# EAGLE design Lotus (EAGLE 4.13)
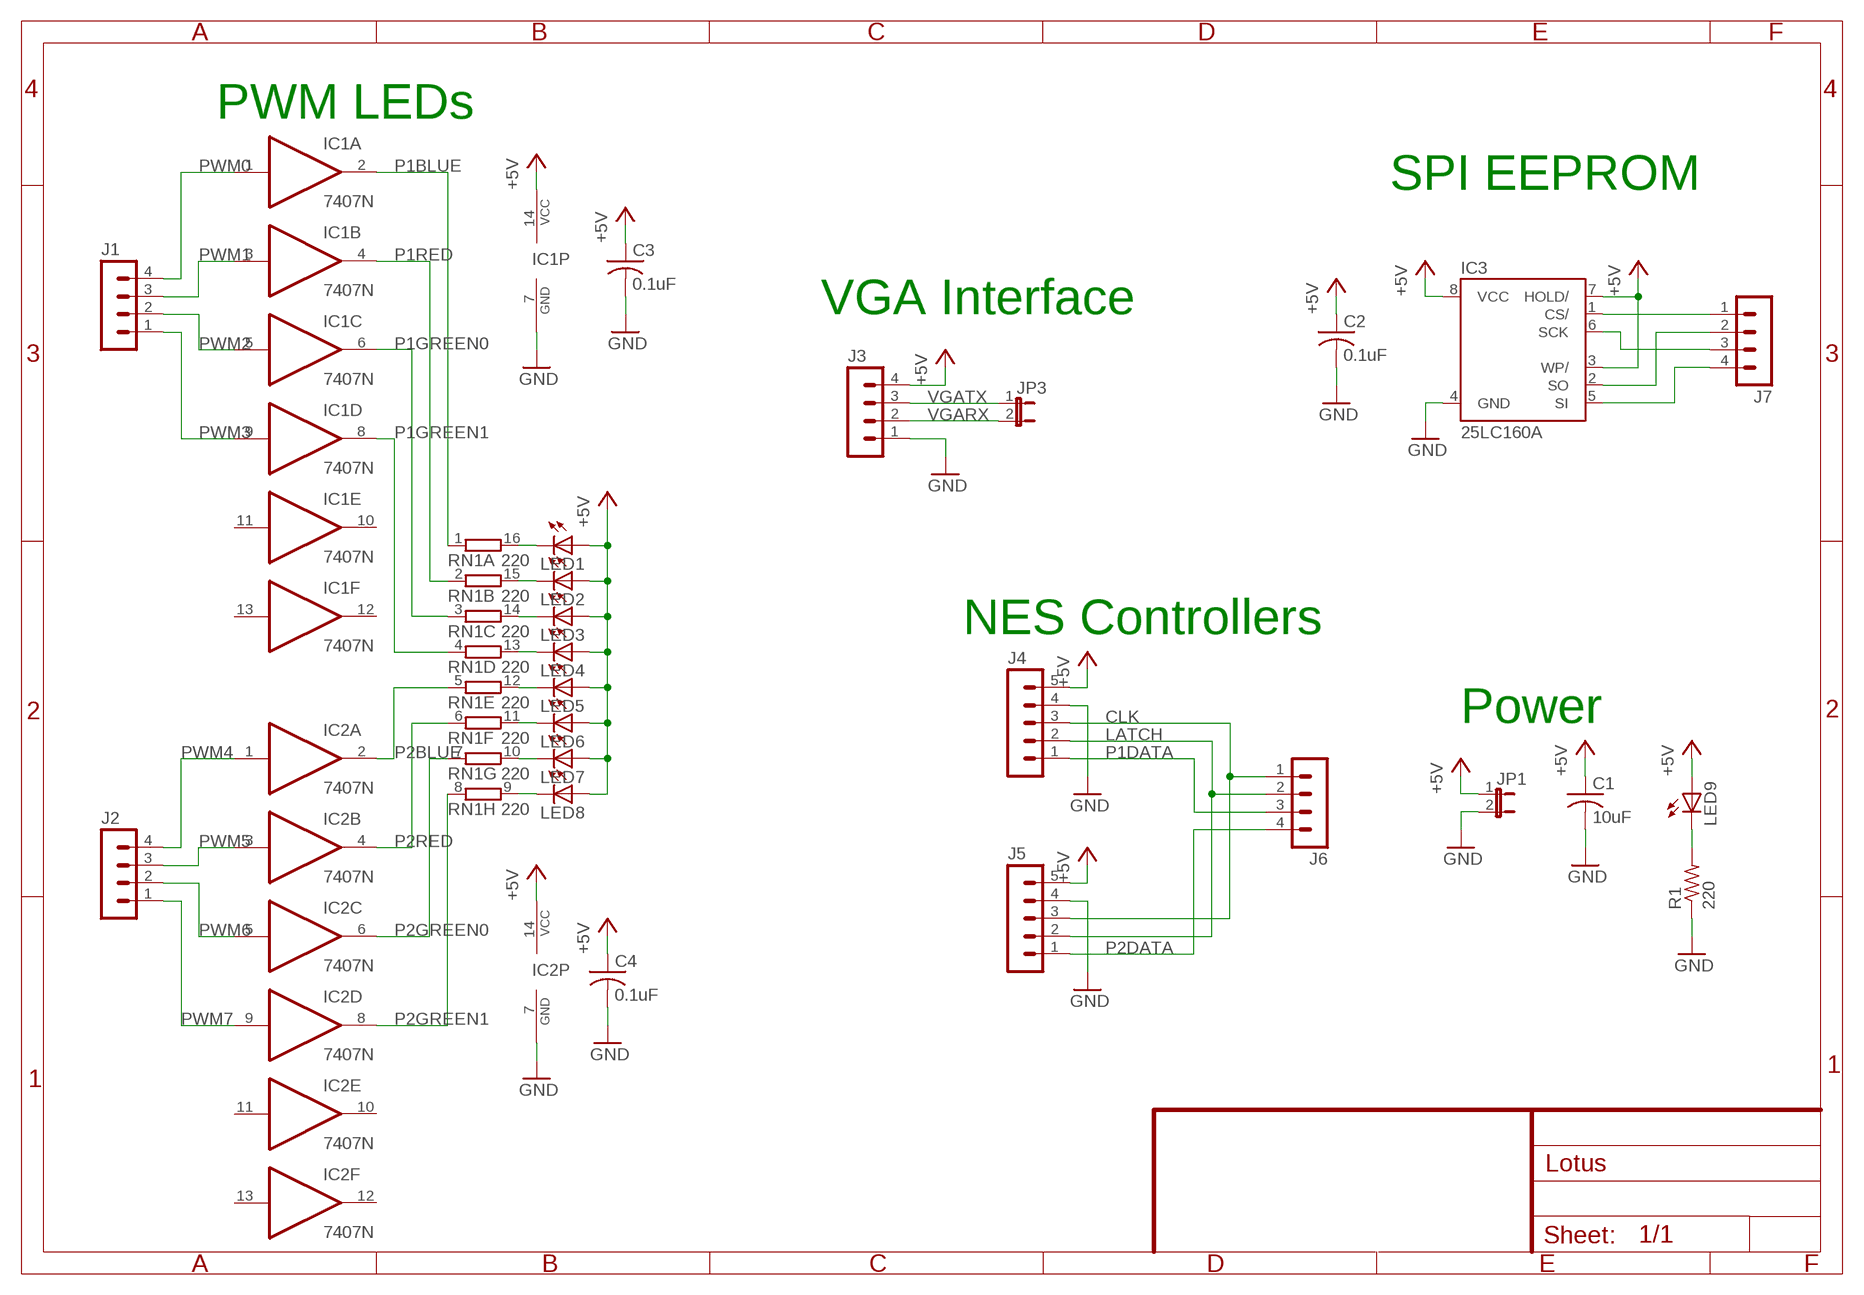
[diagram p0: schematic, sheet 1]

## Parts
C1  10uF  C-USC0805  [C0805]
C2  0.1uF  C-USC0805  [C0805]
C3  0.1uF  C-USC0805  [C0805]
C4  0.1uF  C-USC0805  [C0805]
IC1  7407N  [DIL14]
IC2  7407N  [DIL14]
IC3  25LC160A  AT25P  [DIL08]
J1  MA04-1  [MA04-1]
J2  MA04-1  [MA04-1]
J3  MA04-1  [MA04-1]
J4  MA05-1  [MA05-1]
J5  MA05-1  [MA05-1]
J6  MA04-1  [MA04-1]
J7  MA04-1  [MA04-1]
JP1  JP1EBIGHOLES  [JP1BIG]
JP3  JP1EBIGHOLES  [JP1BIG]
LED1  LEDCHIPLED_1206  [CHIPLED_1206]
LED2  LEDCHIPLED_1206  [CHIPLED_1206]
LED3  LEDCHIPLED_1206  [CHIPLED_1206]
LED4  LEDCHIPLED_1206  [CHIPLED_1206]
LED5  LEDCHIPLED_1206  [CHIPLED_1206]
LED6  LEDCHIPLED_1206  [CHIPLED_1206]
LED7  LEDCHIPLED_1206  [CHIPLED_1206]
LED8  LEDCHIPLED_1206  [CHIPLED_1206]
LED9  LEDCHIPLED_1206  [CHIPLED_1206]
R1  220  R-US_R0603  [R0603]
RN1  220  8R-N  [DIL16]

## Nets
+5V: C1.1 C2.1 C3.1 C4.1 IC1.14(P:VCC) IC2.14(P:VCC) IC3.3(WP/) IC3.7(HOLD/) IC3.8(VCC) J3.4 J4.5 J5.5 JP1.1 LED1.A LED2.A LED3.A LED4.A LED5.A LED6.A LED7.A LED8.A LED9.A
CLK: J4.3 J5.3 J6.1
GND: C1.2 C2.2 C3.2 C4.2 IC1.7(P:GND) IC2.7(P:GND) IC3.4(GND) J3.1 J4.4 J5.4 JP1.2 R1.1
LATCH: J4.2 J5.2 J6.2
N$1: LED1.C RN1.16
N$2: LED2.C RN1.15
N$3: LED3.C RN1.14
N$4: LED4.C RN1.13
N$5: LED5.C RN1.12
N$6: LED6.C RN1.11
N$7: LED7.C RN1.10
N$8: LED8.C RN1.9
N$9: LED9.C R1.2
N$10: IC3.1(CS/) J7.1
N$11: IC3.6(SCK) J7.3
N$12: IC3.2(SO) J7.2
N$13: IC3.5(SI) J7.4
P1BLUE: IC1.2(A:O) RN1.1
P1DATA: J4.1 J6.3
P1GREEN0: IC1.6(C:O) RN1.3
P1GREEN1: IC1.8(D:O) RN1.4
P1RED: IC1.4(B:O) RN1.2
P2BLUE: IC2.2(A:O) RN1.5
P2DATA: J5.1 J6.4
P2GREEN0: IC2.6(C:O) RN1.7
P2GREEN1: IC2.8(D:O) RN1.8
P2RED: IC2.4(B:O) RN1.6
PWM0: IC1.1(A:I) J1.4
PWM1: IC1.3(B:I) J1.3
PWM2: IC1.5(C:I) J1.2
PWM3: IC1.9(D:I) J1.1
PWM4: IC2.1(A:I) J2.4
PWM5: IC2.3(B:I) J2.3
PWM6: IC2.5(C:I) J2.2
PWM7: IC2.9(D:I) J2.1
VGARX: J3.2 JP3.2
VGATX: J3.3 JP3.1
Unconnected: IC1.10(E:O) IC1.11(E:I) IC1.12(F:O) IC1.13(F:I) IC2.10(E:O) IC2.11(E:I) IC2.12(F:O) IC2.13(F:I)

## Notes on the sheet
- PWM LEDs
- SPI EEPROM
- VGA Interface
- NES Controllers
- Power

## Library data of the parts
C1-C4 = rcl:C-US: CAPACITOR, American symbol
IC1 IC2 = 74xx-us:74*07: Hex BUFFER, open collector high-voltage output
IC3 = atmel:AT25*: SPI bus serial EEPROM
J1-J3 J6 J7 = con-lstb:MA04-1: PIN HEADER
J4 J5 = con-lstb:MA05-1: PIN HEADER
JP1 JP3 = jumper:JP1E: JUMPER
LED1-LED9 = led:LED: LED
R1 = rcl:R-US_: RESISTOR, American symbol
RN1 = resistor-dil:8R-N: DIL RESISTOR

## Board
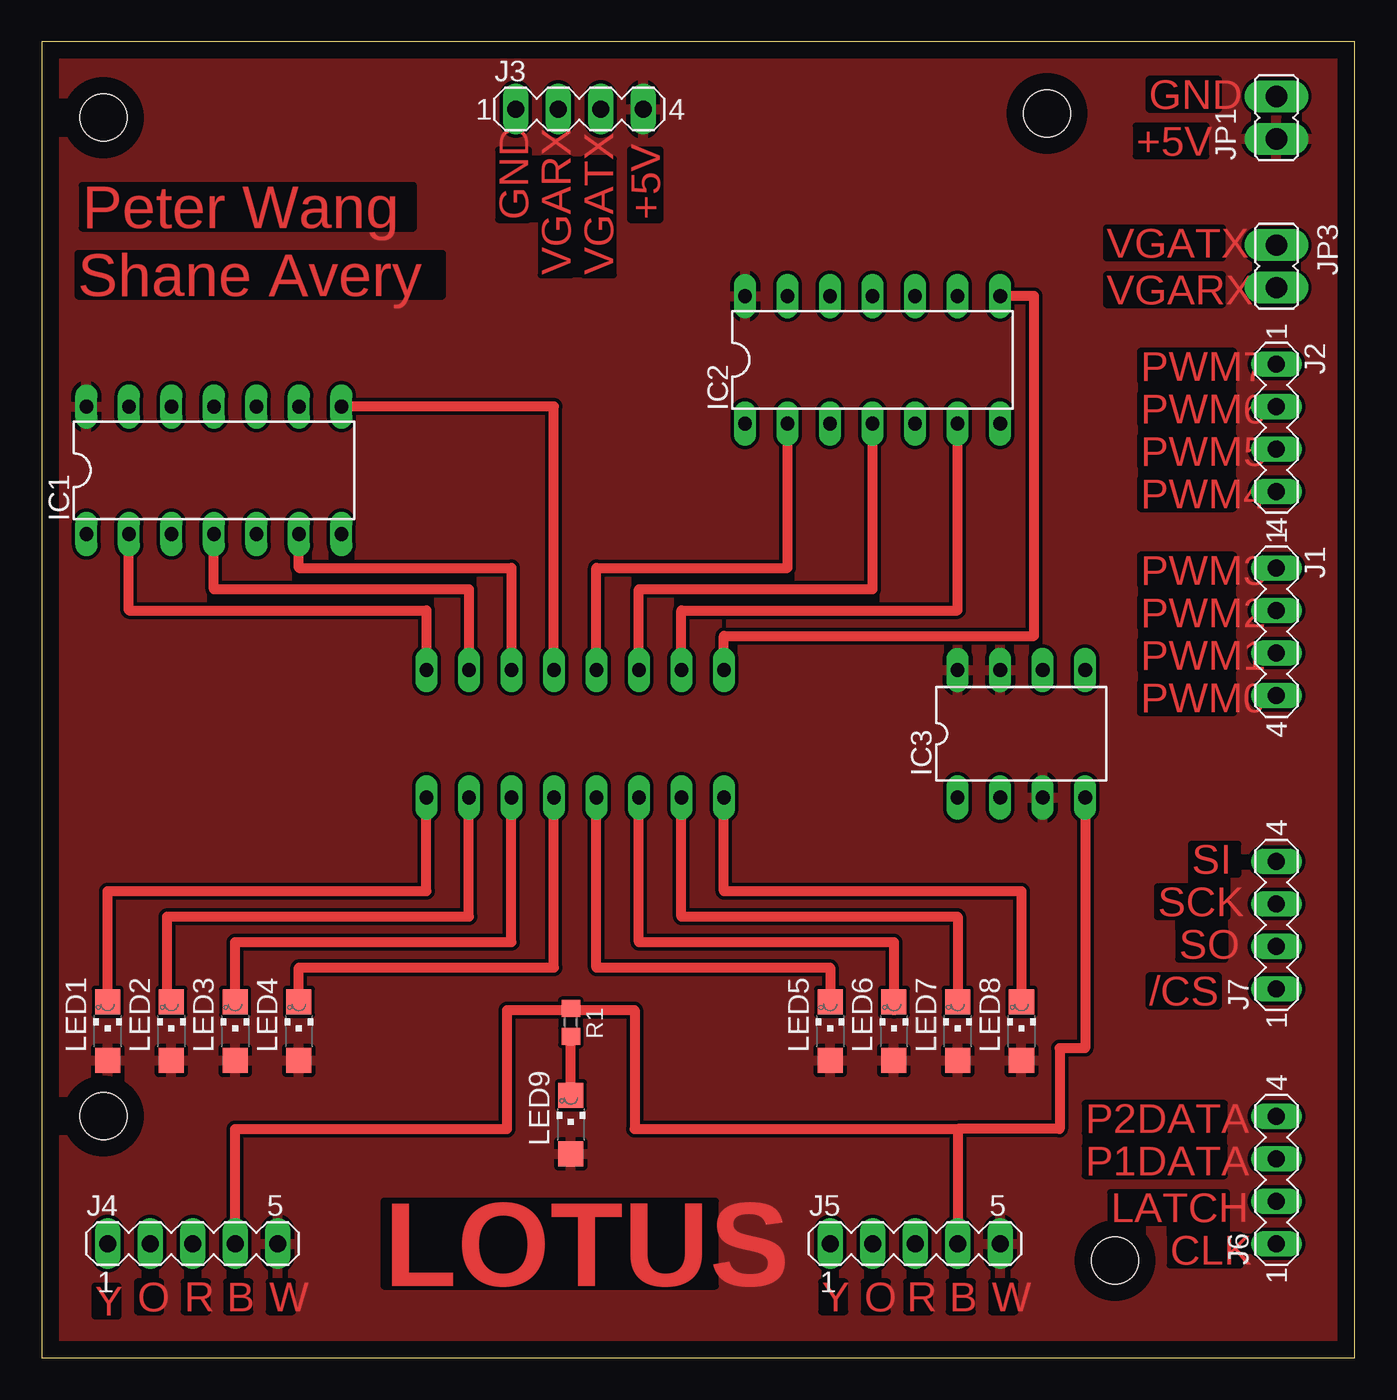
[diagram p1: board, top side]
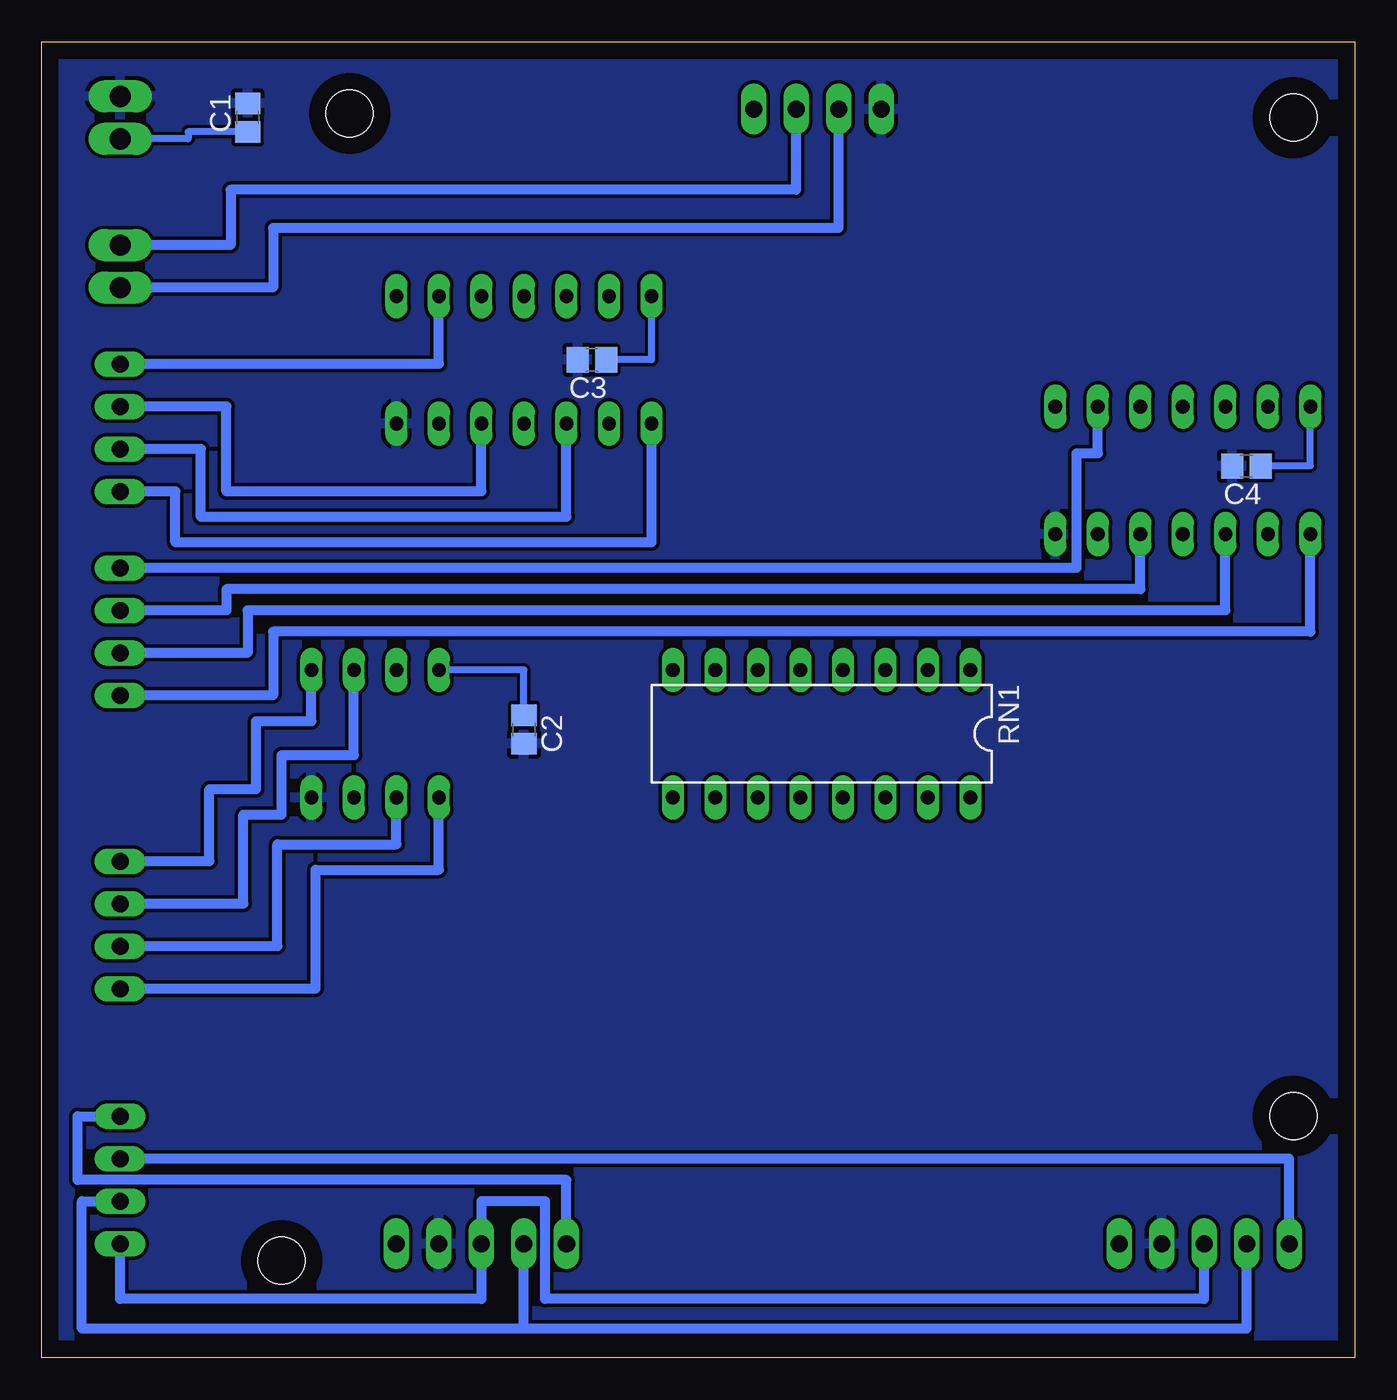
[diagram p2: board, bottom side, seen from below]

Size 78.47 x 78.66 mm. Coordinates in mm from the lower left corner, seen from the top.
Outline: 0,0 78.47,0 78.47,78.66 0,78.66 0,0
Copper layers (1*16): Top 0.035mm / dielectric 1.5mm / Bottom 0.035mm
Design rules "default": minimum track width 10mil, minimum drill 24mil, track to track 8mil, track to pad 8mil, pad to pad 8mil, via to via 8mil, smd to smd 8mil, copper to edge 40mil, drill to drill 8mil, minimum pad ring 10mil, minimum via ring 8mil, stop-mask expansion 4mil, vias tented up to drill 0mil, thermal gap 10mil
Holes 2.8 mm at 3.68,74.13 60.07,74.38 64.13,5.8 3.68,14.44

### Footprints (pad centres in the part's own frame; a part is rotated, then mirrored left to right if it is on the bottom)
C0805 = smd 1.3 x 1.5: 1 -0.85,0; 2 0.85,0
DIL14 = drill 0.813 long: 1 -7.62,-3.81; 2 -5.08,-3.81; 3 -2.54,-3.81; 4 0,-3.81; 5 2.54,-3.81; 6 5.08,-3.81; 7 7.62,-3.81; 8 7.62,3.81; 9 5.08,3.81; 10 2.54,3.81; 11 0,3.81; 12 -2.54,3.81; 13 -5.08,3.81; 14 -7.62,3.81
DIL08 = drill 0.813 long: 1 -3.81,-3.81; 2 -1.27,-3.81; 3 1.27,-3.81; 4 3.81,-3.81; 5 3.81,3.81; 6 1.27,3.81; 7 -1.27,3.81; 8 -3.81,3.81
MA04-1 = drill 1.016 long: 1 -3.81,0; 2 -1.27,0; 3 1.27,0; 4 3.81,0
MA05-1 = drill 1.016 long: 1 -5.08,0; 2 -2.54,0; 3 0,0; 4 2.54,0; 5 5.08,0
JP1BIG = drill 1.27 long: 1 0,-1.27; 2 0,1.27
CHIPLED_1206 = smd 1.5 x 1.5: A 0,-1.75; C 0,1.75
R0603 = smd 1 x 1.1: 1 -0.85,0; 2 0.825,0
DIL16 = drill 0.813 long: 1 -8.89,-3.81; 2 -6.35,-3.81; 3 -3.81,-3.81; 4 -1.27,-3.81; 5 1.27,-3.81; 6 3.81,-3.81; 7 6.35,-3.81; 8 8.89,-3.81; 9 8.89,3.81; 10 6.35,3.81; 11 3.81,3.81; 12 1.27,3.81; 13 -1.27,3.81; 14 -3.81,3.81; 15 -6.35,3.81; 16 -8.89,3.81

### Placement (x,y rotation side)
C1  66.16,74.13 90 bottom
C2  49.65,37.55 270 bottom
C3  45.59,59.65 180 bottom
C4  6.47,53.3 180 bottom
IC1  10.28,53.05 0 top
IC2  49.65,59.65 0 top
IC3  58.54,37.3 0 top
J1  73.78,43.4 270 top
J2  73.78,55.59 270 top
J3  32.13,74.64 0 top
J4  9.01,6.82 0 top
J5  52.19,6.82 0 top
J6  73.78,10.63 90 top
J7  73.78,25.87 90 top
JP1  73.78,74.13 0 top
JP3  73.78,65.24 180 top
LED1  3.93,19.52 0 top
LED2  7.74,19.52 0 top
LED3  11.55,19.52 0 top
LED4  15.36,19.52 0 top
LED5  47.11,19.52 0 top
LED6  50.92,19.52 0 top
LED7  54.73,19.52 0 top
LED8  58.54,19.52 0 top
LED9  31.62,13.93 0 top
R1  31.62,20.03 270 top
RN1  31.87,37.3 180 bottom

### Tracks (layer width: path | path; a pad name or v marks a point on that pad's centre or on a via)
+5V
  Bottom 0.406: C4.1 2.66,53.3 IC1.14 | C3.1 42.03,59.65 IC2.14 | C1.1 69.72,73.28 69.72,72.86 JP1.1 | C2.1 49.65,41.11 IC3.8
  pour Top: 0.63,77.94 77.85,77.94 77.85,0.72 0.63,0.72
CLK
  Bottom 0.61: J6.1 73.78,3.52 52.19,3.52 J5.3 52.19,9.36 48.38,9.36 48.38,3.52 9.01,3.52 J4.3
GND
  Top 0.406: 31.62,20.79 R1.1
  Top 0.61: 54.73,13.68 J5.4 | 54.73,13.68 35.43,13.68 35.43,20.79 31.62,20.79 27.81,20.79 27.81,13.68 11.55,13.68 J4.4 | IC3.4 62.35,18.5 60.83,18.5 60.83,13.68 54.73,13.68
  pour Bottom: 0.38,78.19 78.1,78.19 78.1,0.47 0.38,0.47
LATCH
  Bottom 0.61: J6.2 76.07,9.36 76.07,1.74 49.65,1.74 | 49.65,1.74 J5.2 | J4.2 6.47,1.74 49.65,1.74
N$1
  Top 0.61: LED1.C 3.93,27.9 22.98,27.9 RN1.16
N$2
  Top 0.61: LED2.C 7.49,21.27 7.49,26.38 25.52,26.38 RN1.15
N$3
  Top 0.61: LED3.C 11.55,24.85 28.06,24.85 RN1.14
N$4
  Top 0.61: LED4.C 15.36,23.33 30.6,23.33 RN1.13
N$5
  Top 0.61: LED5.C 47.11,23.33 33.14,23.33 RN1.12
N$6
  Top 0.61: RN1.11 35.68,24.85 50.92,24.85 LED6.C 50.92,20.79
N$7
  Top 0.61: RN1.10 38.22,26.38 54.73,26.38 LED7.C
N$8
  Top 0.61: RN1.9 40.76,27.9 58.54,27.9 LED8.C 58.54,21.04
N$9
  Top 0.61: LED9.C R1.2
N$10
  Bottom 0.61: J7.1 62.1,22.06 62.1,29.17 54.73,29.17 IC3.1
N$11
  Bottom 0.61: J7.3 66.42,27.14 66.42,32.47 64.13,32.47 64.13,36.03 59.81,36.03 IC3.6
N$12
  Bottom 0.61: IC3.2 57.27,30.7 64.38,30.7 64.38,24.6 J7.2
N$13
  Bottom 0.61: J7.4 68.45,29.68 68.45,34 65.65,34 65.65,38.06 62.35,38.06 IC3.5
P1BLUE
  Top 0.61: IC1.2 5.2,44.67 22.98,44.67 RN1.1
P1DATA
  Bottom 0.61: J6.3 3.93,11.9 J4.1
P1GREEN0
  Top 0.61: RN1.3 28.06,47.21 15.36,47.21 IC1.6
P1GREEN1
  Top 0.61: 17.65,56.86 IC1.8 30.6,56.86 RN1.4
P1RED
  Top 0.61: RN1.2 25.52,45.94 10.28,45.94 IC1.4
P2BLUE
  Top 0.61: IC2.2 44.57,47.21 33.14,47.21 RN1.5 33.4,41.11
P2DATA
  Bottom 0.61: J6.4 76.32,14.44 76.32,10.63 47.11,10.63 J5.1
P2GREEN0
  Top 0.61: RN1.7 38.22,44.67 54.73,44.67 IC2.6
P2GREEN1
  Top 0.61: RN1.8 40.76,43.14 59.3,43.14 59.3,63.46 IC2.8
P2RED
  Top 0.61: RN1.6 35.68,45.94 49.65,45.94 IC2.4
PWM0
  Bottom 0.61: J1.4 64.64,39.59 64.64,43.4 2.66,43.4 IC1.1
PWM1
  Bottom 0.61: J1.3 66.16,42.13 66.16,44.67 7.74,44.67 IC1.3
PWM2
  Bottom 0.61: J1.2 67.43,44.67 67.43,45.94 12.82,45.94 IC1.5
PWM3
  Bottom 0.61: J1.1 16.63,47.21 16.63,54.06 15.36,54.06 IC1.9
PWM4
  Bottom 0.61: J2.4 70.48,51.78 70.48,48.73 42.03,48.73 IC2.1
PWM5
  Bottom 0.61: J2.3 68.96,54.32 68.96,50.25 47.11,50.25 IC2.3
PWM6
  Bottom 0.61: J2.2 67.43,56.86 67.43,51.78 52.19,51.78 IC2.5
PWM7
  Bottom 0.61: J2.1 54.73,59.4 IC2.9
VGARX
  Bottom 0.61: JP3.2 64.64,63.97 64.64,67.53 30.86,67.53 J3.2 30.86,74.89
VGATX
  Bottom 0.61: JP3.1 67.18,66.51 67.18,69.81 33.4,69.81 J3.3 33.4,74.89

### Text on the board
Top: GND | +5V | GND | +5V | Peter Wang | VGATX | VGARX | VGATX | Shane Avery | VGARX | PWM7 | PWM6 | PWM5 | PWM4 | PWM3 | PWM2 | PWM1 | PWM0 | SI | SCK | SO | /CS | P2DATA | P1DATA | LATCH | CLK | LOTUS | Y | O | R | B | W | Y | O | R | B | W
